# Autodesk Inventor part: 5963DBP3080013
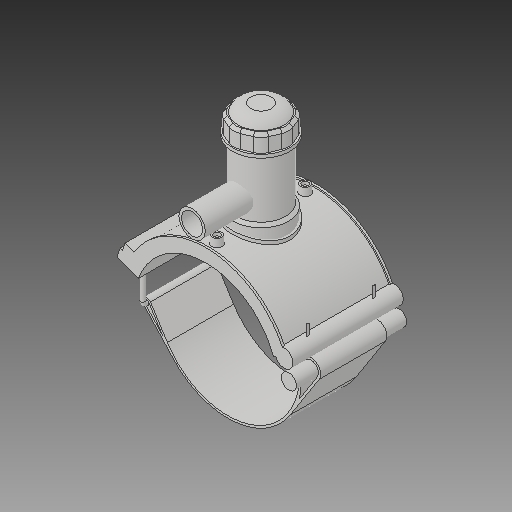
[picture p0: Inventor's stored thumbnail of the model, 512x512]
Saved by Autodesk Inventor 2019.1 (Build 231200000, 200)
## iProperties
Created: 2017-07
Part Number: 5963DBP3080013
Material: Generic
Description: PLASSON TAPPING SADDLE 8''DIPS x 1 1/4''IPS
Document SubType Name: Modeling
Designer: KIM
Density: 1 g/cm^3
Appearance: Default
Author: KIM
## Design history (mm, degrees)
derived "5963DBP_5963BUP.ipt"
feature "Solid1::5963DBP_5963BUP.ipt"
feature "Solid2::5963DBP_5963BUP.ipt"
feature "Solid3::5963DBP_5963BUP.ipt"
tag "TaggingFeature1"
body "Solid1"
body "Solid2"
body "Solid3"
other parameters: "d_" = 228.9, "B_" = 179.832, "L_" = 176.022, "d_t" = 6, "H_2" = 177.038, "H_1" = 65.024, "d_1" = 42.1, "H_" = 109.982, "d1" = 265.524, "d148" = 3.4335, "d160" = 3.4335, "d169" = 3.4335, "d192" = 7.3248, "d0" = 228.9, "d2" = 269.748, "d3" = 57.225, "d4" = 176.022, "d5" = 0, "d6" = 0.1, "d8" = 0, "d19" = 6, "d20" = 6, "d21" = 105.6132, "d23" = 0, "d24" = 52.8066, "d26" = 0, "d27" = 3, "d28" = 3, "d29" = 3, "d30" = 76.3, "d31" = 6, "d32" = 0, "d33" = 0, "d34" = 0.6, "d40" = 138.07248, "d41" = 91.56, "d43" = 0, "d45" = 0, "d47" = 238.3752, "d70" = 15, "d72" = 0, "d73" = 6, "d75" = 5, "d76" = 0, "d77" = 11.445, "d78" = 144.45, "d79" = 15, "d80" = 70.4088, "d82" = 5 deg, "d84" = 4, "d85" = 14, "d86" = 0, "d87" = 3, "d88" = 0, "d89" = 1, "d90" = 1, "d91" = 140.8176, "d92" = 0, "d93" = 0.5, "d94" = 120.47368, "d96" = 270.83448, "d97" = 3.52044, "d98" = 0, "d120" = 140 deg, "d121" = 24.228, "d122" = 20 deg, "d123" = 531.048, "d124" = 159.3144, "d126" = 0, "d143" = 235.767, "d145" = 28.17231, "d149" = 3.4335, "d150" = 30.98954, "d153" = 176.022, "d154" = 0, "d156" = 132.762, "d157" = 160 deg, "d159" = 7.3248, "d161" = 3.4335, "d162" = 105.6132, "d163" = 0, "d164" = 114.45, "d167" = 22.89, "d168" = 129.5239, "d170" = 3.4335, "d172" = 0, "d173" = 1, "d175" = 114.45, "d176" = 20 deg, "d177" = 16.023, "d178" = 36.624, "d180" = 0, "d183" = 14.6496, "d184" = 12.8184, "d185" = 57.20715, "d186" = 57.20715, "d187" = 132.762, "d188" = 10.9872, "d189" = 16.023, "d190" = 0, "d191" = 199.143, "d193" = 7.3248, "d194" = 6.16077, "d195" = 90 deg, "d197" = 0, "d199" = 0, "d200" = 18.312, "d202" = 0, "d203" = 177.038, "d204" = 86.982, "d205" = 64.092, "d206" = 77.826, "d207" = 132.7785, "d208" = 138.08964, "d209" = 164.64534, "d210" = 78.7416, "d211" = 91.56, "d212" = 73.248, "d213" = 39.5766, "d216" = 0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
